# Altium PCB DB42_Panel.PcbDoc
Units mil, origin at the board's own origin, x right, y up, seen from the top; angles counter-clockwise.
Board outline 10094.49 x 7826.77 mil, 8 copper layers (Top Layer, MidLayer1, MidLayer2, GND-Layer5, MidLayer3, 3V3, MidLayer4, Bottom Layer), stack 61.822 mil thick; 0 components, 444 nets, 12 pads, 0 vias.
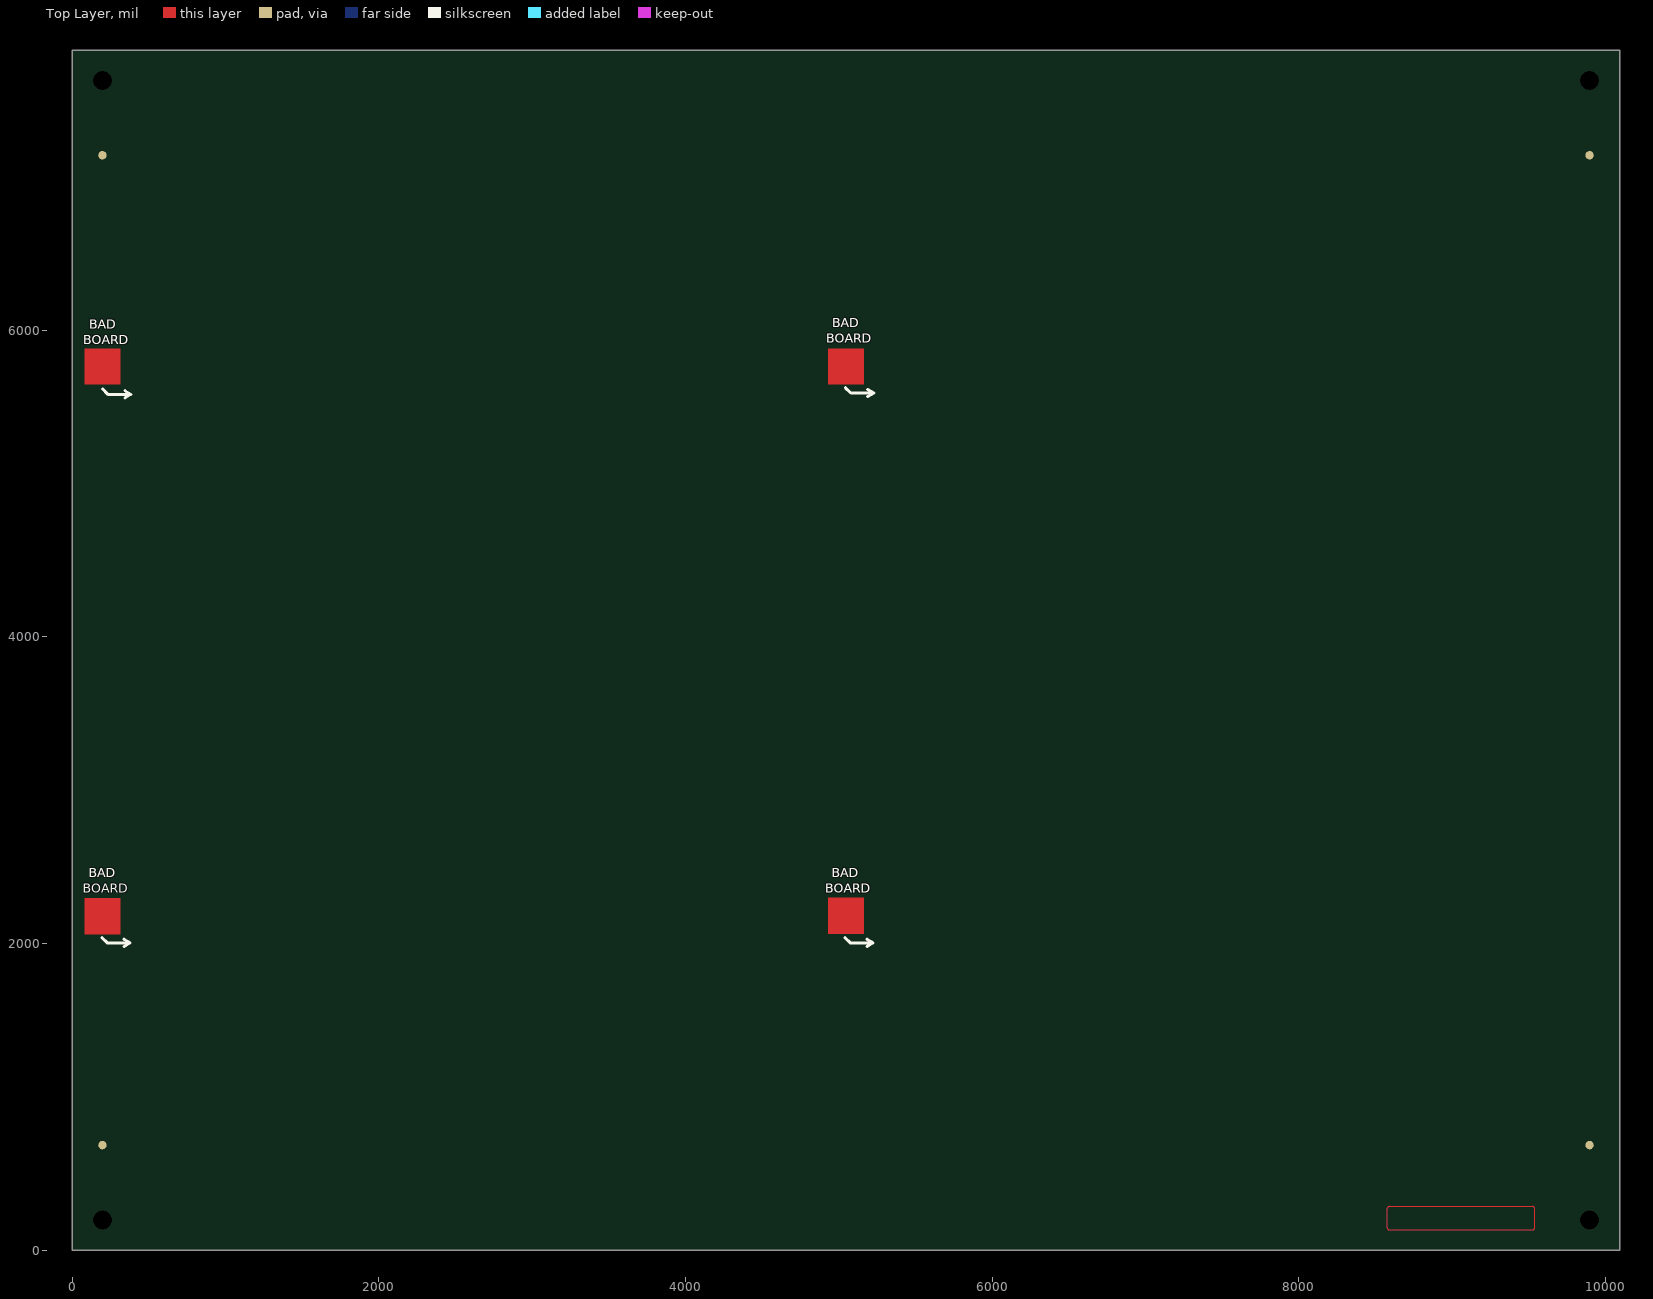
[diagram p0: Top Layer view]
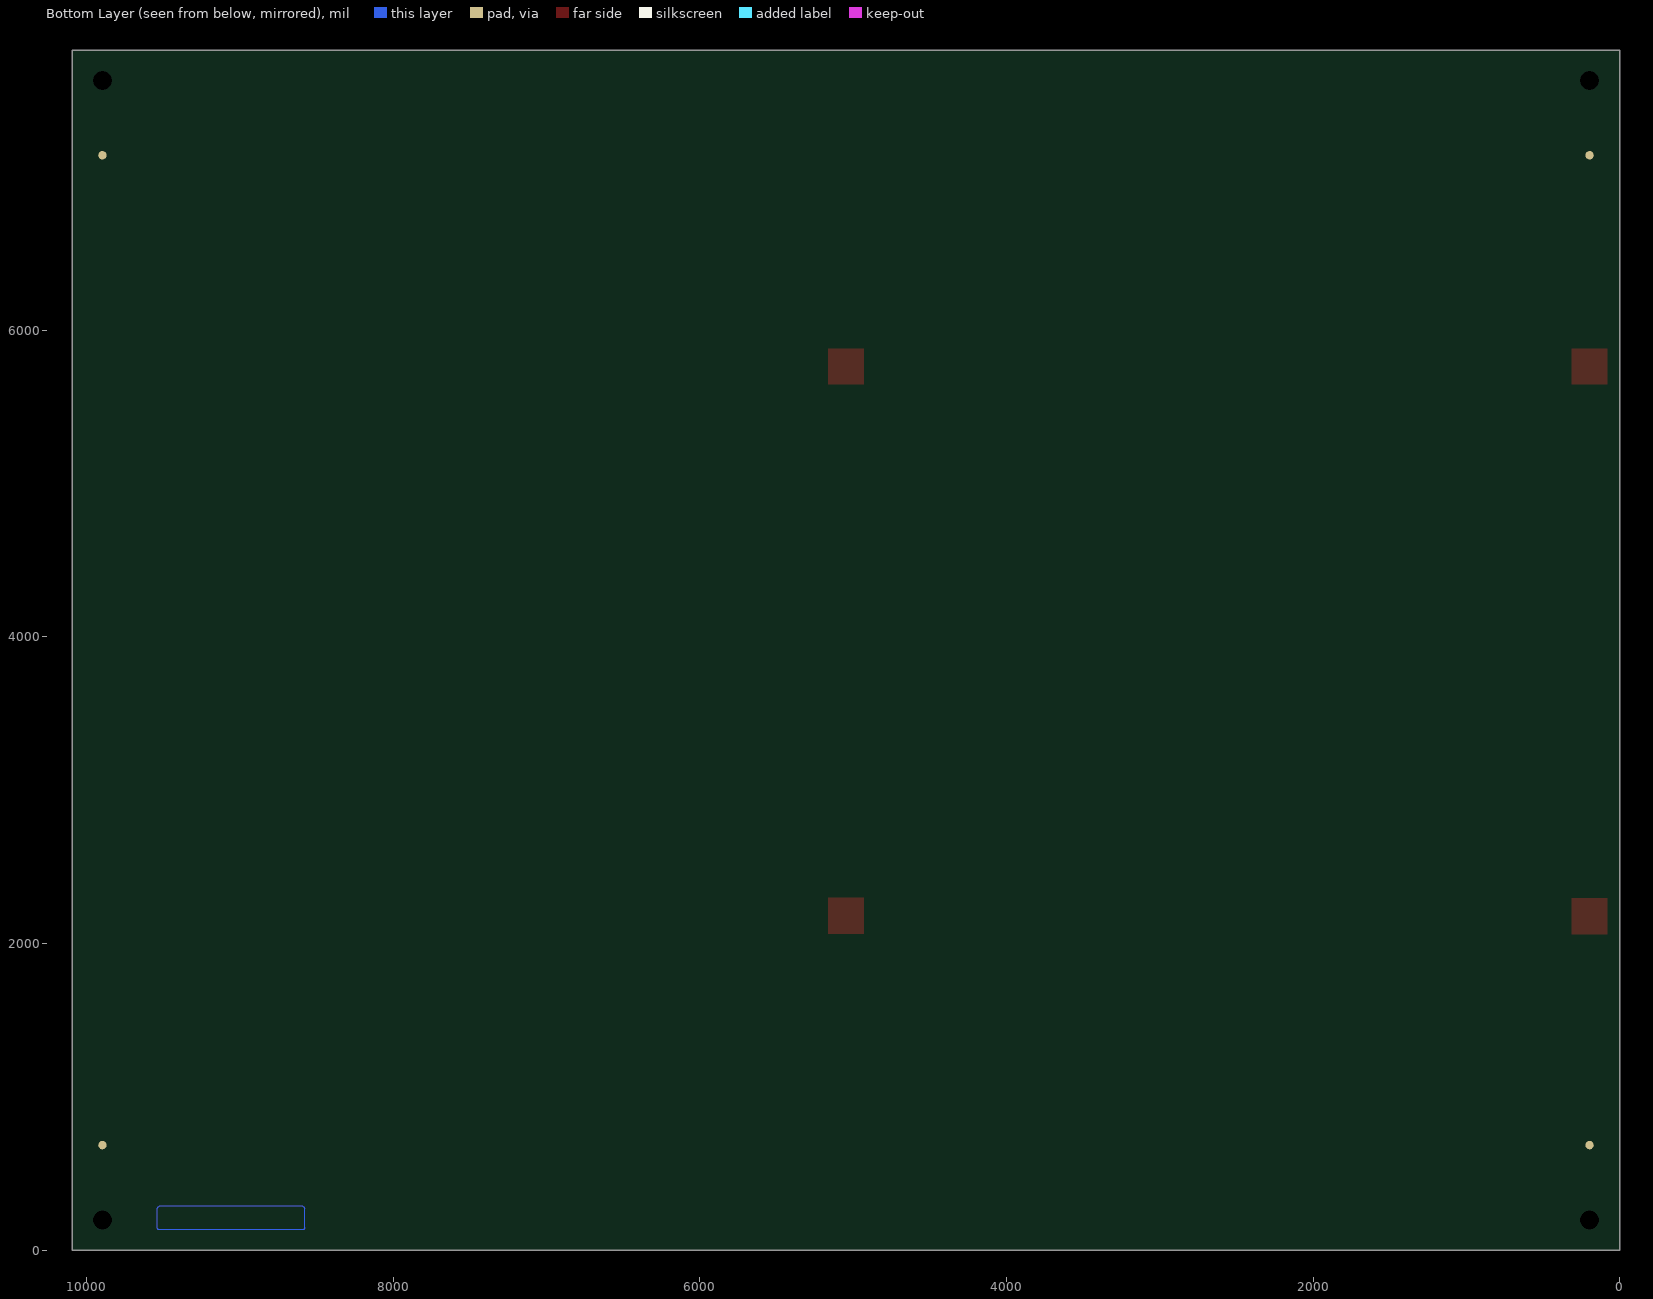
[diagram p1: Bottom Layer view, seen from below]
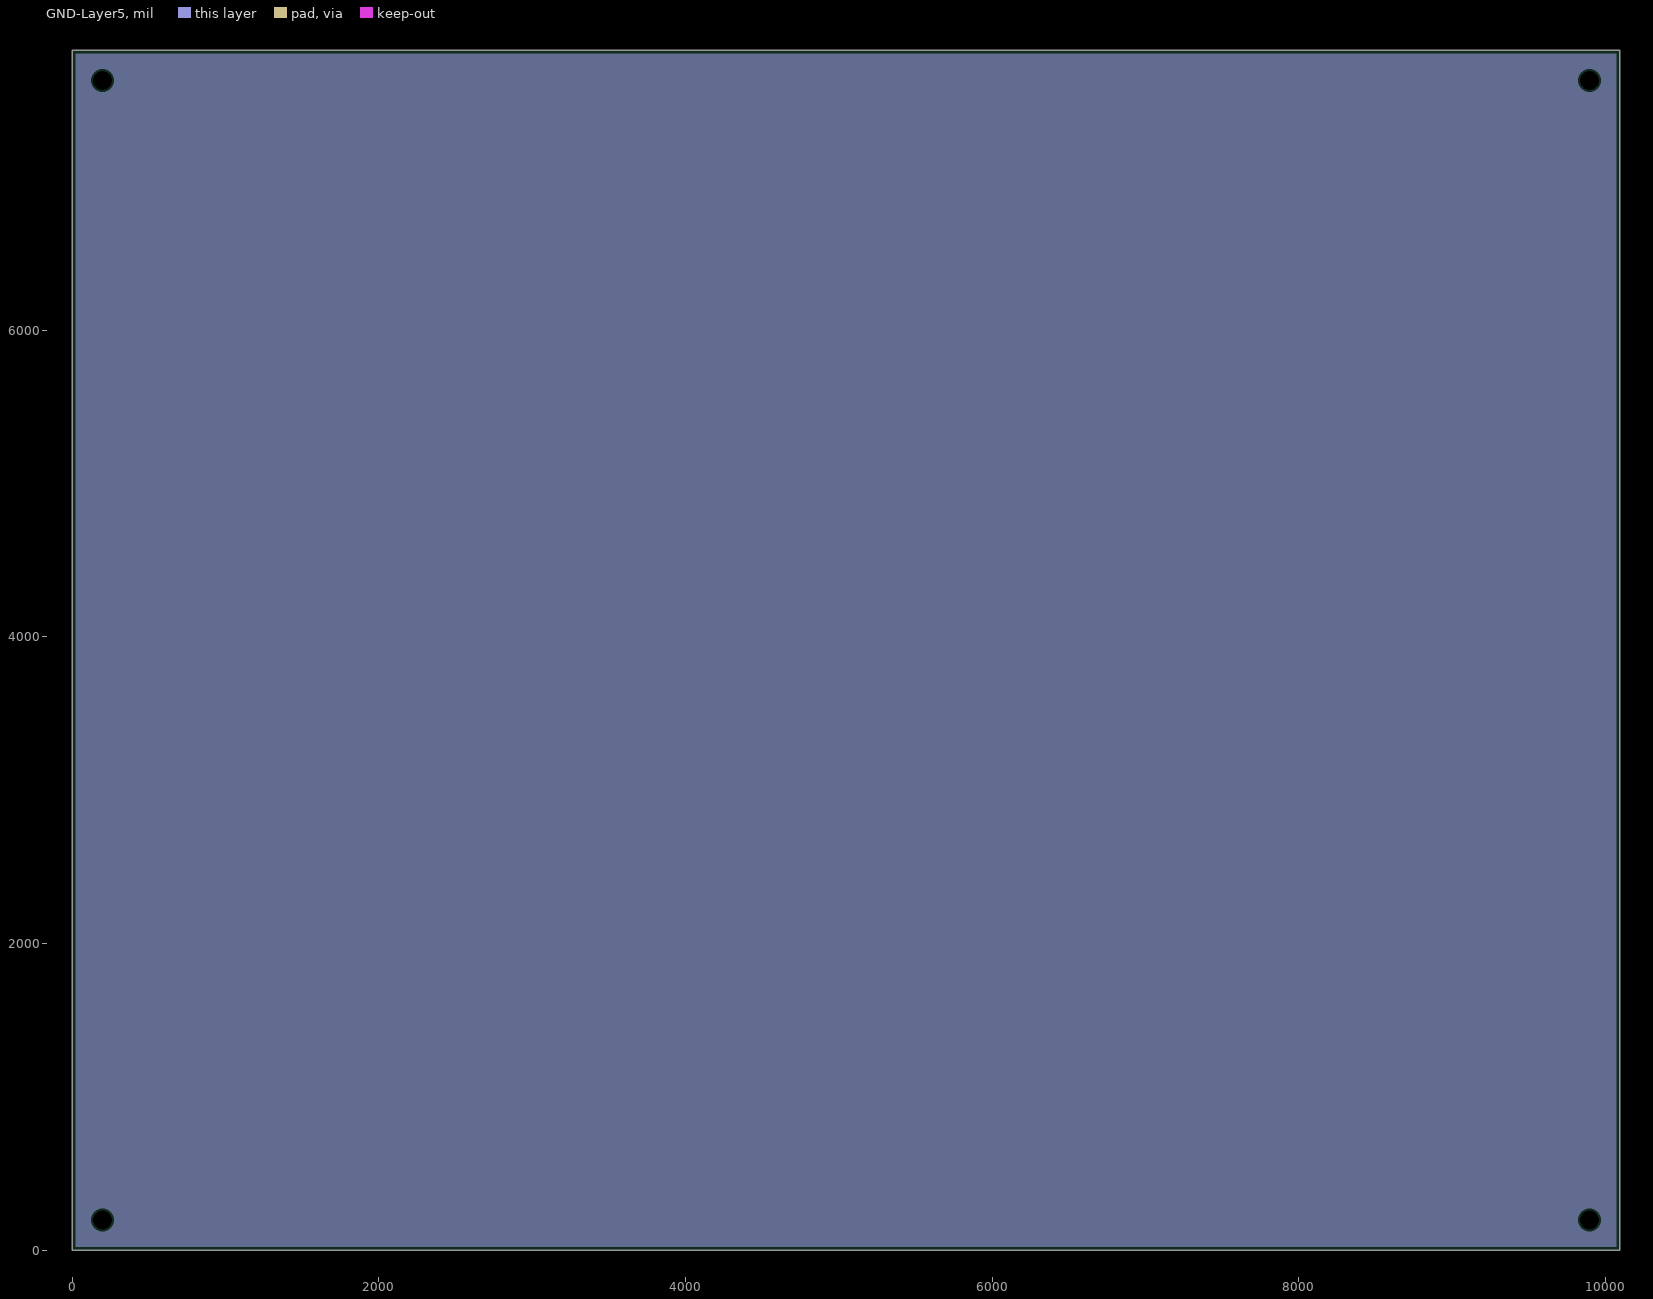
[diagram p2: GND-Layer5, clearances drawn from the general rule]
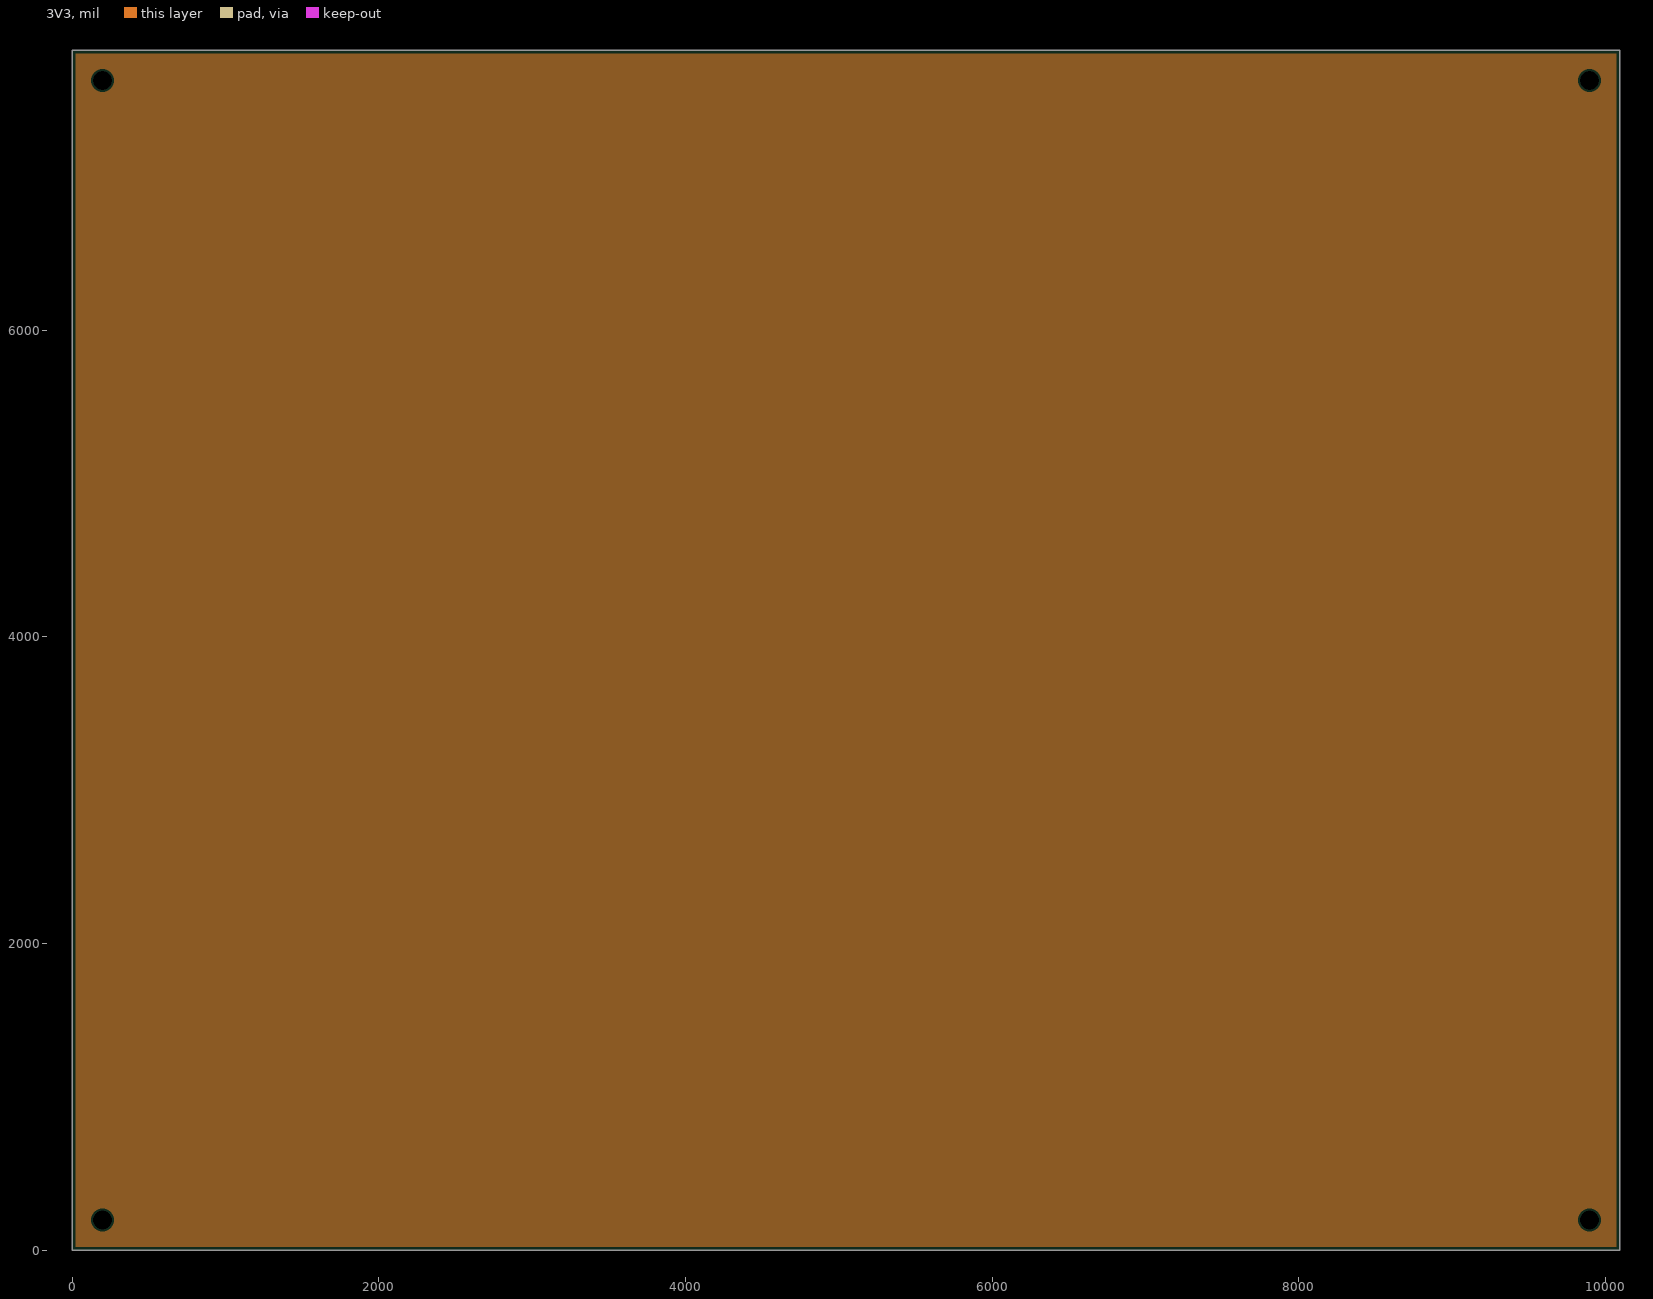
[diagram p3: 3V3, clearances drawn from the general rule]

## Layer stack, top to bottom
Top Layer: signal copper 1.6929
Dielectric: prepreg 5, FR-4, Dk 4.3
MidLayer1: signal copper 1.4016
Dielectric: core 10, FR-4, Dk 4.8
MidLayer2: signal copper 1.4
Dielectric: prepreg 5, FR-4, Dk 4.3
GND-Layer5: plane copper 1.4173
Dielectric: core 10, FR-4, Dk 4.8
MidLayer3: signal copper 1.4
Dielectric: prepreg 5, FR-4, Dk 4.8
3V3: plane copper 1.4173, net 3V3
Dielectric: core 10, FR-4, Dk 4.8
MidLayer4: signal copper 1.4
Dielectric: prepreg 5, FR-4, Dk 4.8
Bottom Layer: signal copper 1.6929

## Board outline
0,0 0,7826.77 10090.55,7826.77 10094.49,7826.77 10094.49,0

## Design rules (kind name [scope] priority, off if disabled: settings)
Clearance Clearance_Poly_Tight [InNamedPolygon('FPGAPWR-TL-1V2') Or InNamedPolygon('FPGAPWR-BL-1V2') Or InNamedPolygon('FPGAPWR-BL-3V3') Or InNamedPolygon('FPGAPWR-BL-2V5A') Or InNamedPolygon('FPGAPWR-BL-2V5B') Or InNamedPolygon('FPGAPWR-BL-2V5C') Or InNamedPolygon('FPGAPWR-BL-2V5D') Or InNamedPolygon('FPGAPWR-ML1-1V2') Or InNamedPolygon('FPGAPWR-BL-2V5E') Or InNamedPolygon('FPGAPWR-BL-3V3' )] p1: gap=5
Clearance Clearance_Polygon [InPolygon] p2: gap=7.87
Clearance "Pad-Pad Clearance Same Net" [IsPad vs IsPad] p3: gap=5
Clearance "Via-Pad Clearance" [IsVia vs IsPad] p4: gap=3.94
Clearance "General Clearance" [All] p5: gap=5
ComponentClearance [All] p1 off: gap=7.87 collisioncheckmode=3 verticalgap=10 showdistances=FALSE
DiffPairsRouting [All] p1: maxlimit=5 minlimit=5 mostfreqgap=5 maxuncoupledlength=200
FabricationTestPointUsage TestPointUsage [All] p1 off: valid=0 allowmultiple=FALSE
FabricationTestpoint Testpoint [All] p1 off: side=3 testpointundercomponent=TRUE minsize=40 maxsize=100 preferedsize=60 minholesize=0 maxholesize=40 preferedholesize=32 testpointgrid=1 allowsidetop=TRUE allowsidebottom=TRUE usegrid=TRUE gridtolerance=0.01
HoleSize [All] p1: absolutevalues=TRUE maxlimit=204.72 minlimit=7.87 maxpercent=80.000 minpercent=20.000
MatchedLengths DiffPair_MatchedLengths [(IsDifferentialPair And (Name = 'DIFF_RX1'))] p1: tolerance=1000 checknetsindiffpair=TRUE checkdiffpairvsdiffpair=TRUE checkothers=TRUE
MinimumAnnularRing MinimumAnnularRing_NonPlated [(ObjectKind = 'Pad') And (HoleDiameter >= '0.7') And (PadIsPlated = 'False')] p1: minimumring=-196.85
MinimumAnnularRing [All] p2: minimumring=5.91
PlaneClearance [All] p1: clearance=11.81
PlaneConnect [All] p1: planeconnectstyle=Direct reliefexpansion=19.68 reliefentries=4 reliefconductorwidth=9.84 reliefairgap=9.84
PolygonConnect PolygonConnect_Via [IsVia] p1: connectstyle=Direct reliefconductorwidth=10 reliefentries=4 polygonreliefangle="90 Angle"
PolygonConnect "PolygonConnect - Heatsink" [(HasFootprint('TO-263') AND InNet('VCCINT'))] p2: connectstyle=Direct reliefconductorwidth=10 reliefentries=4 polygonreliefangle="90 Angle"
PolygonConnect [All] p3: connectstyle=Relief reliefconductorwidth=11.81 reliefentries=4 polygonreliefangle="90 Angle"
RoutingLayers [All] p1: top layer_v5=FALSE mid layer 1_v5=FALSE mid layer 2_v5=FALSE mid layer 3_v5=FALSE mid layer 4_v5=FALSE bottom layer_v5=FALSE
RoutingVias [All] p1: holewidth=11.81 width=23.62 viastyle="Through Hole" minholewidth=11.81 minwidth=23.62 maxholewidth=19.68 maxwidth=35.43
ShortCircuit ShortCircuit_1 [Net = 'No Net' vs Net = 'No Net'] p1: allowed=TRUE
ShortCircuit [All] p2: allowed=FALSE
SilkscreenOverComponentPads [All] p1: minsilkscreentomaskgap=10
SolderMaskExpansion SolderMaskExpansion_Vias [IsVia] p1: expansion=-25.59
SolderMaskExpansion [All] p2: expansion=3.94
Width [All] p1: maxlimit=98.43 minlimit=5 preferedwidth=5
18 further rules are at their usual default settings.

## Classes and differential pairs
component class U_PSU: NT7 R5 R6 TP1 TP2 TP3 TP4
component class U_PSU_MAX1831_1V2: C15 C16 C17 C18 C19 C20 C21 C22 L1_PS R11 R13 R15 R16 R17 TP7 TP8 U2
component class U_Memory_CommonBus: C23_CM C24_CM
net class SRAM_A[20..0]: SRAM_A0 SRAM_A1 SRAM_A2 SRAM_A3 SRAM_A4 SRAM_A5 SRAM_A6 SRAM_A7 SRAM_A8 SRAM_A9 SRAM_A10 SRAM_A11 SRAM_A12 SRAM_A13 SRAM_A14 SRAM_A15 SRAM_A16 SRAM_A17 SRAM_A18
net class EXTEND_C[49..0]: EXTEND_C0 EXTEND_C1 EXTEND_C2 EXTEND_C3 EXTEND_C4 EXTEND_C5 EXTEND_C6 EXTEND_C7 EXTEND_C8 EXTEND_C9 EXTEND_C10 EXTEND_C11 EXTEND_C12 EXTEND_C13 EXTEND_C14 EXTEND_C15 EXTEND_C16 EXTEND_C17 EXTEND_C18 EXTEND_C19 EXTEND_C20 EXTEND_C21 EXTEND_C22 EXTEND_C23 EXTEND_C24 EXTEND_C25 EXTEND_C26 EXTEND_C27 EXTEND_C28 EXTEND_C29 EXTEND_C30 EXTEND_C31 EXTEND_C32 EXTEND_C33 EXTEND_C34 EXTEND_C35 EXTEND_C36 EXTEND_C37 EXTEND_C38 EXTEND_C39 EXTEND_C40 EXTEND_C41 EXTEND_C42 EXTEND_C43 EXTEND_C44 EXTEND_C45 EXTEND_C46 EXTEND_C47 EXTEND_C48 EXTEND_C49
net class EXTEND_B[49..0]: EXTEND_B0 EXTEND_B1 EXTEND_B2 EXTEND_B3 EXTEND_B4 EXTEND_B5 EXTEND_B6 EXTEND_B7 EXTEND_B8 EXTEND_B9 EXTEND_B10 EXTEND_B11 EXTEND_B12 EXTEND_B13 EXTEND_B14 EXTEND_B15 EXTEND_B16 EXTEND_B17 EXTEND_B18 EXTEND_B19 EXTEND_B20 EXTEND_B21 EXTEND_B22 EXTEND_B23 EXTEND_B24 EXTEND_B25 EXTEND_B26 EXTEND_B27 EXTEND_B28 EXTEND_B29 EXTEND_B30 EXTEND_B31 EXTEND_B32 EXTEND_B33 EXTEND_B34 EXTEND_B35 EXTEND_B36 EXTEND_B37 EXTEND_B38 EXTEND_B39 EXTEND_B40 EXTEND_B41 EXTEND_B42 EXTEND_B43 EXTEND_B44 EXTEND_B45 EXTEND_B46 EXTEND_B47 EXTEND_B48 EXTEND_B49
net class EXTEND_A[49..0]: EXTEND_A0 EXTEND_A1 EXTEND_A2 EXTEND_A3 EXTEND_A4 EXTEND_A5 EXTEND_A6 EXTEND_A7 EXTEND_A8 EXTEND_A9 EXTEND_A10 EXTEND_A11 EXTEND_A12 EXTEND_A13 EXTEND_A14 EXTEND_A15 EXTEND_A16 EXTEND_A17 EXTEND_A18 EXTEND_A19 EXTEND_A20 EXTEND_A21 EXTEND_A22 EXTEND_A23 EXTEND_A24 EXTEND_A25 EXTEND_A26 EXTEND_A27 EXTEND_A28 EXTEND_A29 EXTEND_A30 EXTEND_A31 EXTEND_A32 EXTEND_A33 EXTEND_A34 EXTEND_A35 EXTEND_A36 EXTEND_A37 EXTEND_A38 EXTEND_A39 EXTEND_A40 EXTEND_A41 EXTEND_A42 EXTEND_A43 EXTEND_A44 EXTEND_A45 EXTEND_A46 EXTEND_A47 EXTEND_A48 EXTEND_A49
net class DAU_TFT_RED[4..0]: DAU_TFT_RED0 DAU_TFT_RED1 DAU_TFT_RED2 DAU_TFT_RED3 DAU_TFT_RED4
net class DAU_TFT_GREEN[5..0]: DAU_TFT_GREEN0 DAU_TFT_GREEN1 DAU_TFT_GREEN2 DAU_TFT_GREEN3 DAU_TFT_GREEN4 DAU_TFT_GREEN5
net class DAU_TFT_CL[3..1]: DAU_TFT_CL1 DAU_TFT_CL2 DAU_TFT_CL3
net class DAU_TFT_BLUE[4..0]: DAU_TFT_BLUE0 DAU_TFT_BLUE1 DAU_TFT_BLUE2 DAU_TFT_BLUE3 DAU_TFT_BLUE4
net class BUS_A[24..1]: BUS_A1 BUS_A2 BUS_A3 BUS_A4 BUS_A5 BUS_A6 BUS_A7 BUS_A8 BUS_A9 BUS_A10 BUS_A11 BUS_A12 BUS_A13 BUS_A14 BUS_A15 BUS_A16 BUS_A17 BUS_A18 BUS_A19 BUS_A20 BUS_A21 BUS_A22 BUS_A23 BUS_A24
component class U_SRAM_Common: C15_CM C16_CM C17_CM C18_CM C19_CM C20_CM C21_CM C22_CM U4_CM U5_CM
component class U_SDRAM: C7_CM C8_CM C9_CM C10_CM C11_CM C12_CM C13_CM C14_CM U2_CM U3_CM
component class U_FLASH: C1_CM C2_CM C3_CM C4_CM C5_CM C6_CM U1_CM
component class U_Bypass_Board: C1_MB C1_PSU C2_MB C3_MB C4_MB C6_MB
component class U_Bypass_3V3: C38_FP C39_FP C40_FP C41_FP C42_FP C43_FP C44_FP C45_FP C46_FP C47_FP C48_FP C49_FP C50_FP C51_FP C52_FP C53_FP C54_FP C55_FP C56_FP C57_FP C58_FP C59_FP C60_FP C61_FP C62_FP C63_FP C64_FP C65_FP C66_FP C67_FP C68_FP C69_FP C70_FP C71_FP C72_FP C73_FP C74_FP C75_FP C76_FP C77_FP C78_FP C79_FP C80_FP C81_FP C82_FP C83_FP C84_FP C85_FP C86_FP C87_FP C88_FP C89_FP C90_FP C91_FP C92_FP C93_FP C94_FP C95_FP C96_FP C97_FP C98_FP C99_FP C100_FP C101_FP C102_FP C103_FP C104_FP C105_FP C106_FP
component class U_SRAM_Free: C1_M C2_M C2B C3_M C4_M C4B C5_M C5B C6_M C7_M C7B C8_M C8B C9_M C9B C10_M C10B C12_M C12B U7B U8B U18 U20
component class U_MotherBoardConnectors: HDR_B HDR_L HDR_T NT1
component class U_LEDS: C98 LED1 LED2 R19 R21 U9
component class U_SPARTAN3: NT2 NT3 NT4 NT5 NT6 NT8 R1 R2 R3 R4 R7 R8 R12 R14 R18 R20 R22 R23 R24 R25 R26 R27 U1
net class BUS_D[31..0]: BUS_D0 BUS_D1 BUS_D2 BUS_D3 BUS_D4 BUS_D5 BUS_D6 BUS_D7 BUS_D8 BUS_D9 BUS_D10 BUS_D11 BUS_D12 BUS_D13 BUS_D14 BUS_D15 BUS_D16 BUS_D17 BUS_D18 BUS_D19 BUS_D20 BUS_D21 BUS_D22 BUS_D23 BUS_D24 BUS_D25 BUS_D26 BUS_D27 BUS_D28 BUS_D29 BUS_D30 BUS_D31
net class BUS_NBE[3..0]: BUS_NBE0 BUS_NBE1 BUS_NBE2 BUS_NBE3
net class DIP[7..0]: DIP0 DIP1 DIP2 DIP3 DIP4 DIP5 DIP6 DIP7
net class FPGA_ID[3..0]: FPGA_ID0 FPGA_ID1 FPGA_ID2 FPGA_ID3
net class FPGA_M[2..0]: FPGA_M0 FPGA_M1 FPGA_M2
net class IO[35..0]: IO0 IO1 IO2 IO3 IO4 IO5 IO6 IO7 IO8 IO9 IO10 IO11 IO12 IO13 IO14 IO15 IO16 IO17 IO18 IO19 IO20 IO21 IO22 IO23 IO24 IO25 IO26 IO27 IO28 IO29 IO30 IO31 IO32 IO33 IO34 IO35
net class LED[7..0]: LED0 LED1 LED2 LED3 LED4 LED5 LED6 LED7
net class SRAM_D[31..0]: SRAM_D0 SRAM_D1 SRAM_D2 SRAM_D3 SRAM_D4 SRAM_D5 SRAM_D6 SRAM_D7 SRAM_D8 SRAM_D9 SRAM_D10 SRAM_D11 SRAM_D12 SRAM_D13 SRAM_D14 SRAM_D15 SRAM_D16 SRAM_D17 SRAM_D18 SRAM_D19 SRAM_D20 SRAM_D21 SRAM_D22 SRAM_D23 SRAM_D24 SRAM_D25 SRAM_D26 SRAM_D27 SRAM_D28 SRAM_D29 SRAM_D30 SRAM_D31
net class SRAM_NBE[3..0]: SRAM_NBE0 SRAM_NBE1 SRAM_NBE2 SRAM_NBE3
net class SW[4..0]: SW0 SW1 SW2 SW3 SW4
differential pair class DIFF_IN: DIFF_RX0 DIFF_RX1 DIFF_RX2 DIFF_RX3
differential pair class DIFF_OUT: DIFF_TX0 DIFF_TX1 DIFF_TX2 DIFF_TX3
net class PWRNET: 1V2 3V3 5V0 AGND GND
component class U_FPGA_Power: C1_PL C2_PL C3_PL C4_PL C5_PL C6_PL C7_PL C8_PL C9_PL C10_PL C11_PL C12_PL C13_PL C14_PL C15_PL C16_PL L2 L3 L4 L5
component class COMP_1V2: C15 C17 C18 C19 C20 C21 C22 L1_PS NT1 NT7 R13 R17
component class COMP_PLL: C1_PL C2_PL C3_PL C4_PL C5_PL C6_PL C7_PL C8_PL C9_PL C10_PL C11_PL C12_PL C13_PL C14_PL C15_PL C16_PL L2 L3 L4 L5
component class U_Bypass_1V2: C1_FP C2_FP C3_FP C4_FP C5_FP C6_FP C7_FP C8_FP C9_FP C10_FP C11_FP C12_FP C13_FP C14_FP C15_FP C16_FP C17_FP C18_FP C19_FP C20_FP C21_FP C22_FP C23_FP C24_FP C25_FP C26_FP C27_FP C28_FP C29_FP C30_FP C31_FP
net class FPGACONF: CONF_DONE DATA0 DCLK FPGA_CCLK FPGA_DIN FPGA_DONE FPGA_INIT FPGA_M0 FPGA_M1 FPGA_PROGRAM FPGA_TCK FPGA_TDI FPGA_TDO FPGA_TMS MSEL0 MSEL1 NCONFIG NSTATUS TCK TDI TDO TMS
net class PLL: VCCA_PLL1 VCCA_PLL2 VCCA_PLL3 VCCA_PLL4
component class DaughterBoard_FPGA: MH1 MH2 MH3
component class MOUNTS-PCB: MH1 MH2 MH3

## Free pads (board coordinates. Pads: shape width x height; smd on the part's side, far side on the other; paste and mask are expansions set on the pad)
  round 106 hole 126 unplated mask+35: 126N(196.85,196.85) 126N(196.85,7629.92) 126N(9897.64,7629.92)
  round 105.98 hole 125.98 unplated mask+35: 126N(9897.64,196.85)
  round 55 smd far side paste-100 mask+52: fidbot(196.85,685.04) fidbot(196.85,7141.73) fidbot(9897.64,685.04) fidbot(9897.64,7141.73)
  round 55 smd paste-100 mask+52: fidtop(196.85,685.04) fidtop(196.85,7141.73) fidtop(9897.64,685.04) fidtop(9897.64,7141.73)

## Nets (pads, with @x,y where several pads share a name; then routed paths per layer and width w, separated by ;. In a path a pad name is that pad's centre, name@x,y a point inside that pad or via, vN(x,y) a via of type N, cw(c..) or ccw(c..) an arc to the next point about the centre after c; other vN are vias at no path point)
1V2: 
3V3: 
5V0: 
AGND: 
BUS_A1: 
BUS_A2: 
BUS_A3: 
BUS_A4: 
BUS_A5: 
BUS_A6: 
BUS_A7: 
BUS_A8: 
BUS_A9: 
BUS_A10: 
BUS_A11: 
BUS_A12: 
BUS_A13: 
BUS_A14: 
BUS_A15: 
BUS_A16: 
BUS_A17: 
BUS_A18: 
BUS_A19: 
BUS_A20: 
BUS_A21: 
BUS_A22: 
BUS_A23: 
BUS_A24: 
BUS_D0: 
BUS_D1: 
BUS_D2: 
BUS_D3: 
BUS_D4: 
BUS_D5: 
BUS_D6: 
BUS_D7: 
BUS_D8: 
BUS_D9: 
BUS_D10: 
BUS_D11: 
BUS_D12: 
BUS_D13: 
BUS_D14: 
BUS_D15: 
BUS_D16: 
BUS_D17: 
BUS_D18: 
BUS_D19: 
BUS_D20: 
BUS_D21: 
BUS_D22: 
BUS_D23: 
BUS_D24: 
BUS_D25: 
BUS_D26: 
BUS_D27: 
BUS_D28: 
BUS_D29: 
BUS_D30: 
BUS_D31: 
BUS_FLASH_NBUSY: 
BUS_FLASH_NCS: 
BUS_FLASH_NRESET: 
BUS_NBE0: 
BUS_NBE1: 
BUS_NBE2: 
BUS_NBE3: 
BUS_NOE: 
BUS_NWE: 
BUS_RAM_NCS: 
BUS_SDRAM_CKE: 
BUS_SDRAM_CLK: 
BUS_SDRAM_NCAS: 
BUS_SDRAM_NCS: 
BUS_SDRAM_NRAS: 
BUZZER: 
CAN_RXD: 
CAN_TXD: 
COMP: 
CONF_DONE: 
DATA0: 
DAU_RESET_SW: 
DAU_SPARE: 
DAU_TFT_BLIGHT: 
DAU_TFT_BLUE0: 
DAU_TFT_BLUE1: 
DAU_TFT_BLUE2: 
DAU_TFT_BLUE3: 
DAU_TFT_BLUE4: 
DAU_TFT_CL1: 
DAU_TFT_CL2: 
DAU_TFT_CL3: 
DAU_TFT_DISP_ON: 
DAU_TFT_GREEN0: 
DAU_TFT_GREEN1: 
DAU_TFT_GREEN2: 
DAU_TFT_GREEN3: 
DAU_TFT_GREEN4: 
DAU_TFT_GREEN5: 
DAU_TFT_IRQ: 
DAU_TFT_M: 
DAU_TFT_MUX: 
DAU_TFT_POL: 
DAU_TFT_RED0: 
DAU_TFT_RED1: 
DAU_TFT_RED2: 
DAU_TFT_RED3: 
DAU_TFT_RED4: 
DAU_TFT_STH: 
DAU_TFT_STV: 
DCLK: 
DIP0: 
DIP1: 
DIP2: 
DIP3: 
DIP4: 
DIP5: 
DIP6: 
DIP7: 
EXTEND_A0: 
EXTEND_A1: 
EXTEND_A2: 
EXTEND_A3: 
EXTEND_A4: 
EXTEND_A5: 
EXTEND_A6: 
EXTEND_A7: 
EXTEND_A8: 
EXTEND_A9: 
EXTEND_A10: 
EXTEND_A11: 
EXTEND_A12: 
EXTEND_A13: 
EXTEND_A14: 
EXTEND_A15: 
EXTEND_A16: 
EXTEND_A17: 
EXTEND_A18: 
EXTEND_A19: 
EXTEND_A20: 
EXTEND_A21: 
EXTEND_A22: 
EXTEND_A23: 
EXTEND_A24: 
EXTEND_A25: 
EXTEND_A26: 
EXTEND_A27: 
EXTEND_A28: 
EXTEND_A29: 
EXTEND_A30: 
EXTEND_A31: 
EXTEND_A32: 
EXTEND_A33: 
EXTEND_A34: 
EXTEND_A35: 
EXTEND_A36: 
EXTEND_A37: 
EXTEND_A38: 
EXTEND_A39: 
EXTEND_A40: 
EXTEND_A41: 
EXTEND_A42: 
EXTEND_A43: 
EXTEND_A44: 
EXTEND_A45: 
EXTEND_A46: 
EXTEND_A47: 
EXTEND_A48: 
EXTEND_A49: 
EXTEND_B0: 
EXTEND_B1: 
EXTEND_B2: 
EXTEND_B3: 
EXTEND_B4: 
EXTEND_B5: 
EXTEND_B6: 
EXTEND_B7: 
EXTEND_B8: 
EXTEND_B9: 
EXTEND_B10: 
EXTEND_B11: 
EXTEND_B12: 
EXTEND_B13: 
EXTEND_B14: 
EXTEND_B15: 
EXTEND_B16: 
EXTEND_B17: 
EXTEND_B18: 
EXTEND_B19: 
EXTEND_B20: 
EXTEND_B21: 
EXTEND_B22: 
EXTEND_B23: 
EXTEND_B24: 
EXTEND_B25: 
EXTEND_B26: 
EXTEND_B27: 
EXTEND_B28: 
EXTEND_B29: 
EXTEND_B30: 
EXTEND_B31: 
EXTEND_B32: 
EXTEND_B33: 
EXTEND_B34: 
EXTEND_B35: 
EXTEND_B36: 
EXTEND_B37: 
EXTEND_B38: 
EXTEND_B39: 
EXTEND_B40: 
EXTEND_B41: 
EXTEND_B42: 
EXTEND_B43: 
EXTEND_B44: 
EXTEND_B45: 
EXTEND_B46: 
EXTEND_B47: 
EXTEND_B48: 
EXTEND_B49: 
EXTEND_C0: 
EXTEND_C1: 
EXTEND_C2: 
EXTEND_C3: 
EXTEND_C4: 
EXTEND_C5: 
EXTEND_C6: 
EXTEND_C7: 
EXTEND_C8: 
EXTEND_C9: 
EXTEND_C10: 
EXTEND_C11: 
EXTEND_C12: 
EXTEND_C13: 
EXTEND_C14: 
EXTEND_C15: 
EXTEND_C16: 
EXTEND_C17: 
EXTEND_C18: 
EXTEND_C19: 
EXTEND_C20: 
EXTEND_C21: 
EXTEND_C22: 
EXTEND_C23: 
EXTEND_C24: 
EXTEND_C25: 
EXTEND_C26: 
EXTEND_C27: 
EXTEND_C28: 
EXTEND_C29: 
EXTEND_C30: 
EXTEND_C31: 
EXTEND_C32: 
EXTEND_C33: 
EXTEND_C34: 
EXTEND_C35: 
EXTEND_C36: 
EXTEND_C37: 
EXTEND_C38: 
EXTEND_C39: 
EXTEND_C40: 
EXTEND_C41: 
EXTEND_C42: 
EXTEND_C43: 
EXTEND_C44: 
EXTEND_C45: 
EXTEND_C46: 
EXTEND_C47: 
EXTEND_C48: 
EXTEND_C49: 
FB: 
FPGA_CCLK: 
FPGA_CLK: 
FPGA_CLK1: 
FPGA_CLK2: 
FPGA_DIN: 
FPGA_DONE: 
FPGA_ID0: 
FPGA_ID1: 
FPGA_ID2: 
FPGA_ID3: 
FPGA_INIT: 
FPGA_INSTALLED: 
FPGA_M0: 
FPGA_M1: 
FPGA_M2: 
FPGA_PROG_CLK: 
FPGA_PROG_PWR_ON: 
FPGA_PROGRAM: 
FPGA_TCK: 
FPGA_TDI: 
FPGA_TDO: 
FPGA_TMS: 
GND: 
IO0: 
IO1: 
IO2: 
IO3: 
IO4: 
IO5: 
IO6: 
IO7: 
IO8: 
IO9: 
IO10: 
IO11: 
IO12: 
IO13: 
IO14: 
IO15: 
IO16: 
IO17: 
IO18: 
IO19: 
IO20: 
IO21: 
IO22: 
IO23: 
IO24: 
IO25: 
IO26: 
IO27: 
IO28: 
IO29: 
IO30: 
IO31: 
IO32: 
IO33: 
IO34: 
IO35: 
KBCLOCK: 
KBDATA: 
LED0: 
LED1: 
LED2: 
LED3: 
LED4: 
LED5: 
LED6: 
LED7: 
LED_PGM: 
LED_PWR: 
LX: 
MOUSECLOCK: 
MOUSEDATA: 
MSEL0: 
MSEL1: 
NCONFIG: 
NetLED2_1: 
NetR15_1: 
NEXUS_TCK: 
NEXUS_TDI: 
NEXUS_TDO: 
NEXUS_TMS: 
NSTATUS: 
REF_1V2: 
REF_CLK: 
RS232_CTS: 
RS232_RTS: 
RS232_RX: 
RS232_TX: 
SCL: 
SDA: 
SDRAM_FEEDBACK: 
SPI_CLK: 
SPI_DIN: 
SPI_DOUT: 
SPI_MODE: 
SPI_SEL: 
SRAM_A0: 
SRAM_A1: 
SRAM_A2: 
SRAM_A3: 
SRAM_A4: 
SRAM_A5: 
SRAM_A6: 
SRAM_A7: 
SRAM_A8: 
SRAM_A9: 
SRAM_A10: 
SRAM_A11: 
SRAM_A12: 
SRAM_A13: 
SRAM_A14: 
SRAM_A15: 
SRAM_A16: 
SRAM_A17: 
SRAM_A18: 
SRAM_D0: 
SRAM_D1: 
SRAM_D2: 
SRAM_D3: 
SRAM_D4: 
SRAM_D5: 
SRAM_D6: 
SRAM_D7: 
SRAM_D8: 
SRAM_D9: 
SRAM_D10: 
SRAM_D11: 
SRAM_D12: 
SRAM_D13: 
SRAM_D14: 
SRAM_D15: 
SRAM_D16: 
SRAM_D17: 
SRAM_D18: 
SRAM_D19: 
SRAM_D20: 
SRAM_D21: 
SRAM_D22: 
SRAM_D23: 
SRAM_D24: 
SRAM_D25: 
SRAM_D26: 
SRAM_D27: 
SRAM_D28: 
SRAM_D29: 
SRAM_D30: 
SRAM_D31: 
SRAM_NBE0: 
SRAM_NBE1: 
SRAM_NBE2: 
SRAM_NBE3: 
SRAM_NCS: 
SRAM_NOE: 
SRAM_NWE: 
STATUS_LED: 
SW0: 
SW1: 
SW2: 
SW3: 
SW4: 
TCK: 
TDI: 
TDO: 
TMS: 
TOFF: 
VCCA_PLL1: 
VCCA_PLL2: 
VCCA_PLL3: 
VCCA_PLL4: 
VCCX: 
VCCX_REF: 
VFILT: 

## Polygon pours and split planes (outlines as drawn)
no net on GND-Layer5 (split plane): 10074.39,20.1 20.1,20.1 20.1,7806.67 10074.39,7806.67
3V3 on 3V3 (split plane): 10074.39,20.1 20.1,20.1 20.1,7806.67 10074.39,7806.67

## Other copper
Top Layer:
  rectangle: 78.74,5645.67 314.96,5881.89
  rectangle: 4929.13,5645.67 5165.35,5881.89
  rectangle: 4929.13,2062.99 5165.35,2299.21
  rectangle: 78.74,2059.06 314.96,2295.28
  rectangle: 78.74,5645.67 314.96,5881.89
  rectangle: 4929.13,5645.67 5165.35,5881.89
  rectangle: 4929.13,2062.99 5165.35,2299.21
  rectangle: 78.74,2059.06 314.96,2295.28
Multi-Layer:
  lines w8: 8579.44,144.44 ccw(c8592.44,144.44) 8592.44,131.44 9525.77,131.44 ccw(c9525.77,144.44) 9538.77,144.44 9538.77,271.95 ccw(c9525.77,271.95) 9525.77,284.95 8592.44,284.95 ccw(c8592.44,271.95) 8579.44,271.95 8579.44,144.44
  text "DB42SVN9250" at 8606.44,160.22 h150

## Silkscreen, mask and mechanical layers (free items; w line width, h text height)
Top Overlay:
  lines w20: 228.35,2003.94 377.95,2003.94 ; 228.35,2003.94 192.91,2039.37 228.35,2003.94 ; 228.35,2003.94 377.95,2003.94 ; 232.28,5582.68 196.85,5618.11 232.28,5582.68 ; 232.28,5582.68 381.89,5582.68 ; 232.28,5582.68 381.89,5582.68 ; 377.95,2003.94 338.58,2027.56 377.95,2003.94 ; 377.95,2003.94 338.58,1980.31 377.95,2003.94 ; 381.89,5582.68 342.52,5559.06 381.89,5582.68 ; 381.89,5582.68 342.52,5606.3 381.89,5582.68 ; 5074.8,2003.94 5224.41,2003.94 ; 5074.8,2003.94 5039.37,2039.37 5074.8,2003.94 ; 5074.8,2003.94 5224.41,2003.94 ; 5078.74,5590.55 5228.35,5590.55 ; 5078.74,5590.55 5043.31,5625.98 5078.74,5590.55 ; 5078.74,5590.55 5228.35,5590.55 ; 5224.41,2003.94 5185.04,2027.56 5224.41,2003.94 ; 5224.41,2003.94 5185.04,1980.31 5224.41,2003.94 ; 5228.35,5590.55 5188.98,5614.17 5228.35,5590.55 ; 5228.35,5590.55 5188.98,5566.93 5228.35,5590.55
  text "BAD" at 4956.69,6019.68 h60
  text "BAD" at 4956.69,6019.68 h60
  text "BAD" at 110.24,6011.81 h60
  text "BAD" at 110.24,6011.81 h60
  text "BOARD" at 4917.32,5917.32 h60
  text "BOARD" at 4917.32,5917.32 h60
  text "BOARD" at 70.87,5909.45 h60
  text "BOARD" at 70.87,5909.45 h60
  text "BAD" at 106.3,2433.07 h60
  text "BAD" at 106.3,2433.07 h60
  text "BAD" at 4952.76,2433.07 h60
  text "BAD" at 4952.76,2433.07 h60
  text "BOARD" at 66.93,2330.71 h60
  text "BOARD" at 4913.39,2330.71 h60
  text "BOARD" at 4913.39,2330.71 h60
Top Solder:
  rectangle: 78.74,5645.67 314.96,5881.89
  rectangle: 4929.13,5645.67 5165.35,5881.89
  rectangle: 4929.13,2062.99 5165.35,2299.21
  rectangle: 78.74,2059.06 314.96,2295.28
  rectangle: 78.74,5645.67 314.96,5881.89
  rectangle: 4929.13,5645.67 5165.35,5881.89
  rectangle: 4929.13,2062.99 5165.35,2299.21
  rectangle: 78.74,2059.06 314.96,2295.28
  lines w8: 8579.44,144.44 ccw(c8592.44,144.44) 8592.44,131.44 9525.77,131.44 ccw(c9525.77,144.44) 9538.77,144.44 9538.77,271.95 ccw(c9525.77,271.95) 9525.77,284.95 8592.44,284.95 ccw(c8592.44,271.95) 8579.44,271.95 8579.44,144.44
  text "DB42SVN9250" at 8606.44,160.22 h150
Bottom Solder:
  lines w8: 8579.44,144.44 ccw(c8592.44,144.44) 8592.44,131.44 9525.77,131.44 ccw(c9525.77,144.44) 9538.77,144.44 9538.77,271.95 ccw(c9525.77,271.95) 9525.77,284.95 8592.44,284.95 ccw(c8592.44,271.95) 8579.44,271.95 8579.44,144.44
  text "DB42SVN9250" at 8606.44,160.22 h150
6. FabNotes:
  drawing of 1029 lines, arcs and shapes, not listed
  text "DAUGHTER-BOARD PANEL" at 12915,11218.98 h49.21
  text "DESIGN INFORMATION" at 10700.86,11218.22 h49.21
  text "BOARD NAME:" at 12180.86,11218.22 h49.21
  text "BOARD TECHNOLOGY" at 10700.86,11118.22 h49.21
  text "BOARD SIZE (REFER ALSO PROFILING INFORMATION)" at 12600.86,11118.22 h49.21
  text "5.0" at 10784.37,11032.05 h49.21
  text "256.40" at 12707.95,11028.7 h49.21
  text "12.0" at 11322.87,11025.24 h49.21
  text "198.80mm" at 13613.46,11024.76 h49.21
  text "5.0" at 11872.87,11020.24 h49.21
  text "RECOMMENDED LAYUP" at 7167.32,10999.72 h49.21
  text "X" at 13335.86,10998.22 h49.21
  text "(MIN. TRACK/   PADS  /   CLEARANCE     IN 0.001'')" at 10640.86,10918.22 h49.21
  text "MINIMUM ANNULAR RING 0.05MM (0.002'') EXTERNAL PER IPC-2221 CLASS 3 LEVEL C AND IS THE" at 10700.87,10818.23 h49.21
  text "MANUFACTURING REGISTRATION ALLOWANCE" at 10700.86,10728.22 h49.21
  text "LAND SIZE CALCULATION MINIMUM - NOMINAL HOLE SIZE + 0.508MM (0.020'')" at 10700.86,10618.22 h49.21
  text "LAYER STACK CONFIGURATION" at 6747.09,10595.28 h49.21
  text "CIRCUIT TYPE:" at 10700.86,10438.22 h49.21
  text "SS" at 11600.86,10438.22 h49.21
  text "DS" at 12300.86,10438.22 h49.21
  text "X" at 12875.86,10438.22 h49.21
  text "PTH" at 13000.86,10438.22 h49.21
  text "ML" at 13430.86,10438.22 h49.21
  text "X" at 13580.86,10438.22 h49.21
  text "No. of Layers" at 13700.86,10438.22 h49.21
  text "8" at 14384.37,10432.05 h49.21
  text "FINGER CONNECTOR DIM PER:" at 10700.86,10318.22 h49.21
  text "AS SHOWN" at 13700.86,10318.22 h49.21
  text "8 LAYER BUILD" at 7178.8,10313.28 h49.21
  text "No. OFF TOTAL" at 11360.86,10208.22 h49.21
  text "ONE SIDE" at 13000.86,10208.22 h49.21
  text "BOTH SIDES" at 13700.86,10198.22 h49.21
  text "X" at 12177.72,10097.15 h49.21
  text "VIAS:" at 10700.86,10093.22 h49.21
  text "NONE" at 11150.86,10093.22 h49.21
  text "X" at 11480.86,10093.22 h49.21
  text "FEED THRU'" at 11600.86,10093.22 h49.21
  text "TENTED" at 12300.86,10093.22 h49.21
  text "BURIED LAYER SEQUENCE" at 13000.86,10093.22 h49.21
  text "-  COPPER CLAD" at 7849.09,9984 h29.53
  text "-  35 Micron H.T.E 1.4mil" at 8277.09,9984.02 h29.53
  text "TL" at 6803.56,9979 h49.21
  text "UNIQUE DRILL" at 11600.86,9973.22 h49.21
  text "2 SIZE" at 12300.86,9973.22 h49.21
  text "BLIND LAYER SEQUENCE" at 13000.86,9973.22 h49.21
  text "TOP LAYER" at 6302.33,9956 h49.21
  text "-  PRE-PREG" at 7874.09,9929 h29.53
  text "-  1080 5mil" at 8277.09,9927.99 h29.53
  text "Layer Stack Manager (PCB)" at 12095.86,9883.22 h49.21
  text "X" at 13580.86,9883.22 h49.21
  text "AS SHOWN" at 13700.86,9883.22 h49.21
  text "LAYER CONSTRUCTION PER:" at 10700.86,9878.22 h49.21
  text "MID LAYER 1" at 6302.34,9837.56 h49.21
  text "L1" at 6803.56,9834.06 h49.21
  text "-  COPPER CLAD" at 7848.33,9831.9 h29.53
  text "-  35 Micron H.T.E 1.4mil" at 8277.09,9832.01 h29.53
  text "-  CORE" at 7874.09,9779.08 h29.53
  text "-  10mil" at 8277.09,9779.02 h29.53
  text "Altium Designer 6.8" at 13694.53,9773.5 h49.21
  text "ARTWORK:" at 10700.86,9768.22 h49.21
  text "MANUAL" at 11600.86,9768.22 h49.21
  text "DIGITISED" at 12300.86,9768.22 h49.21
  text "X" at 12880.86,9768.22 h49.21
  text "CAD" at 13000.86,9768.22 h49.21
  text "TYPE" at 13430.86,9768.22 h49.21
  text "-  35 Micron H.T.E 1.4mil" at 8277.09,9725 h29.53
  text "-  COPPER CLAD" at 7848.33,9724.4 h29.53
  text "MID LAYER 2" at 6303.24,9717.09 h49.21
  text "L2" at 6803.24,9717.09 h49.21
  text "-  1080 5mil" at 8277.09,9675 h29.53
  text "-  PRE-PREG" at 7873.33,9673.46 h29.53
  text "ARTWORK/PATTERN MASTER LIST" at 10700.86,9583.22 h49.21
  text "P1" at 6803.24,9577.09 h49.21
  text "-  COPPER CLAD" at 7847.56,9576.35 h29.53
  text "-  35 Micron H.T.E 1.4mil" at 8277.09,9575 h29.53
  text "INTERNAL PLANE 1" at 6118.54,9573.54 h49.21
  text "-  CORE" at 7873.32,9523.53 h29.53
  text "-  10mil" at 8277.09,9522.99 h29.53
  text "DESCRIPTION" at 10750.86,9488.22 h49.21
  text "DRAWING No./CAD FILE REF." at 11485.86,9488.22 h49.21
  text "LAYER NAME" at 13110.86,9488.22 h49.21
  text "GERBER FILE REF" at 13927.87,9485.23 h49.21
  text "-  COPPER CLAD" at 7847.56,9468.85 h29.53
  text "-  35 Micron H.T.E 1.4mil" at 8277.09,9467.99 h29.53
  text "MID LAYER 3" at 6282.32,9454.72 h49.21
  text "L3" at 6797.32,9454.72 h49.21
  text "-  PRE-PREG" at 7872.56,9417.91 h29.53
  text "-  1080 5mil" at 8277.09,9417.99 h29.53
  text "PCB FILE" at 10690.86,9388.22 h49.21
  text "2x2 Peripheral Panel" at 11492.4,9385.94 h49.21
  text "PcbDoc" at 12722.87,9385.23 h49.21
  text "INTERNAL PLANE 2" at 6092.32,9329.72 h49.21
  text "P2" at 6792.32,9329.72 h49.21
  text "-  COPPER CLAD" at 7846.8,9320.8 h29.53
  text "-  35 Micron H.T.E 1.4mil" at 8277.09,9321.02 h29.53
  text "Top Paste Mask" at 13044.88,9288.22 h49.21
  text "GTP" at 12769.31,9286.28 h49.21
  text "GTP" at 14722.87,9285.23 h49.21
  text "GERBER FILE" at 10690.86,9283.22 h49.21
  text "-  CORE" at 7872.56,9267.98 h29.53
  text "-  10mil" at 8277.09,9267.99 h29.53
  text "-  COPPER CLAD" at 7846.8,9213.3 h29.53
  text "-  35 Micron H.T.E 1.4mil" at 8277.09,9212.99 h29.53
  text "MID LAYER 4" at 6301.74,9205.99 h49.21
  text "L4" at 6801.74,9205.99 h49.21
  text "GTO" at 12769.31,9187.85 h49.21
  text "GTO" at 14720.86,9187.23 h49.21
  text "Top Overlay" at 13044.88,9186.21 h49.21
  text "GERBER FILE" at 10690.86,9183.22 h49.21
  text "-  PRE-PREG" at 7871.8,9162.36 h29.53
  text "-  1080 5mil" at 8277.09,9162.01 h29.53
  text "Top Solder Mask" at 13044.88,9090.23 h49.21
  text "GTS" at 12769.31,9089.43 h49.21
  text "GTS" at 14722.87,9085.23 h49.21
  text "GERBER FILE" at 10690.86,9083.22 h49.21
  text "BL" at 6801.73,9065.98 h49.21
  text "-  35 Micron H.T.E 1.4mil" at 8277.09,9066.02 h29.53
  text "BOTTOM LAYER" at 6224.84,9065.67 h49.21
  text "-  COPPER CLAD" at 7846.04,9065.25 h29.53
  text "Board Layer 1" at 13925.2,8992.13 h49.21
  text "Top Layer" at 13044.88,8988.23 h49.21
  text "GTL" at 14722.87,8985.23 h49.21
  text "GERBER FILE" at 10690.86,8983.22 h49.21
  text "GTL" at 12769.31,8983.13 h49.21
  text "GERBER FILE" at 10690.86,8885.58 h49.21
  text "Mid Layer 1" at 13053.86,8789.06 h49.21
  text "1.6mm" at 7486.25,8788.08 h49.21
  text "G1" at 12767.72,8787.4 h49.21
  text "Board Layer 2" at 13933.07,8787.4 h49.21
  text "G1" at 14724.41,8787.4 h49.21
  text "GERBER FILE" at 10690.86,8785.58 h49.21
  text "TOTAL BOARD THICKNESS: APPROX" at 6205.16,8782.2 h49.21
  text "(61.2mil)" at 7752.4,8782.2 h49.21
  text "Board Layer 3" at 13927.87,8694.57 h49.21
  text "G2" at 12767.72,8688.98 h49.21
  text "G2" at 14724.41,8688.98 h49.21
  text "Mid Layer 2" at 13053.86,8686.69 h49.21
  text "GERBER FILE" at 10690.86,8685.58 h49.21
  text "V-GROOVE" at 9763.78,8657.48 h49.21 r90
  text "V-GROOVE" at 456.69,8606.3 h49.21 r90
  text "Board Layer 4" at 13923.94,8592.2 h49.21
  text "GP1" at 12767.72,8590.55 h49.21
  text "GP1" at 14724.41,8590.55 h49.21
  text "GND" at 13042.03,8588.29 h49.21
  text "GERBER FILE" at 10690.86,8585.58 h49.21
  text "Board Layer 5" at 13925.2,8496.06 h49.21
  text "G3" at 12762.52,8486.26 h49.21
  text "G3" at 14719.21,8486.26 h49.21
  text "GERBER FILE" at 10690.86,8484 h49.21
  text "Mid Layer 3" at 13038.11,8481.97 h49.21
  text "Board Layer 6" at 13923.94,8395.35 h49.21
  text "GP2" at 12757.52,8384.68 h49.21
  text "GP2" at 14714.21,8384.68 h49.21
  text "GERBER FILE" at 10690.86,8384 h49.21
  text "V-GROOVE" at 4917.32,8381.89 h49.21 r90
  text "V-GROOVE" at 5311.02,8381.89 h49.21 r90
  text "VCC" at 13031.5,8381.89 h49.21
  text "G4" at 12767.72,8291.34 h49.21
  text "Board Layer 7" at 13921.26,8291.34 h49.21
  text "G4" at 14724.41,8291.34 h49.21
  text "Mid Layer 4" at 13045.98,8289.06 h49.21
  text "GERBER FILE" at 10690.86,8284 h49.21
  text "GERBER FILE" at 10690.86,8184 h49.21
  text "BOTTOM LAYER" at 13037.75,8089.79 h49.21
  text "GBL" at 12762.19,8086.91 h49.21
  text "GBL" at 14715.75,8086.8 h49.21
  text "GERBER FILE" at 10690.86,8086.37 h49.21
  text "Board Layer 8" at 13913.39,8086.61 h49.21
  text "GBS" at 12762.19,7992.42 h49.21
  text "Bottom Solder Mask" at 13037.75,7991.8 h49.21
  text "GBS" at 14715.75,7986.8 h49.21
  text "GERBER FILE" at 10690.86,7986.37 h49.21
  text "GBO" at 12762.19,7890.06 h49.21
  text "Bottom Overlay" at 13037.75,7889.79 h49.21
  text "GBO" at 14715.75,7886.8 h49.21
  text "GERBER FILE" at 10690.86,7886.37 h49.21
  text "GBP" at 14715.75,7791.8 h49.21
  text "Bottom Paste Mask" at 13037.75,7789.79 h49.21
  text "GBP" at 12762.19,7787.85 h49.21
  text "GERBER FILE" at 10690.86,7786.37 h49.21
  text "APERTURE LIST" at 10690.86,7588.48 h49.21
  text "APR" at 12762.24,7585.48 h49.21
  text "DRILL REPORT" at 10690.86,7488.48 h49.21
  text "DRR" at 12762.24,7485.48 h49.21
  text "DRILL FILE" at 10680.39,7385.84 h49.21
  text "DRL" at 12757.32,7380.17 h49.21
  text "V-GROOVE" at -1188.98,7322.83 h49.21
  text "TXT" at 12751.26,7285.44 h49.21
  text "EXCELLON DRILL" at 10677.44,7282.49 h49.21
  text "MATERIAL:" at 10700.86,7077.56 h49.21
  text "GLASS FIBRE EPOXY RESIN NEMA GRADE FR4-08 (IPC-4101) - WITH TG170" at 11710.87,7067.56 h49.21
  text "X" at 11605.86,7062.56 h49.21
  text "THICKNESS:" at 11010.86,6952.56 h49.21
  text "0.8mm" at 11710.86,6952.56 h49.21
  text "1.2mm" at 12405.86,6952.56 h49.21
  text "1.6mm" at 13100.85,6952.58 h49.21
  text "2.4mm" at 13800.86,6952.56 h49.21
  text "3.2mm" at 14500.86,6952.56 h49.21
  text "X" at 13005.86,6947.56 h49.21
  text "2" at 12854.33,6838.58 h49.21
  text "TOLERANCE:" at 11005.86,6832.56 h49.21
  text "OTHER +/-" at 13800.86,6832.56 h49.21
  text "X" at 11605.86,6827.56 h49.21
  text "IN A/W IPC-D-300G CLASS" at 11732.36,6824.68 h49.21
  text "2" at 12854.33,6716.54 h49.21
  text "BOW & TWIST:" at 11005.35,6712.56 h49.21
  text "AS SHOWN" at 13805.86,6707.56 h49.21
  text "IN A/W IPC-D-300G CLASS" at 11732.36,6704.68 h49.21
  text "X" at 11605.86,6702.56 h49.21
  text "COPPER THICKNESS (FINISHED)" at 10909.45,6594.49 h49.21
  text "18um" at 11710.86,6492.56 h49.21
  text "35um" at 12775.86,6492.56 h49.21
  text "70um" at 13810.86,6492.56 h49.21
  text "OUTER:" at 11051.18,6488.19 h49.21
  text "X" at 12667.87,6484.57 h49.21
  text "INNER SIGNAL:" at 10909.45,6377.95 h49.21
  text "18um" at 11710.86,6372.56 h49.21
  text "35um" at 12775.86,6372.56 h49.21
  text "70um" at 13810.86,6372.56 h49.21
  text "X" at 11606.3,6370.08 h49.21
  text "INNER PWR:" at 11051.18,6251.97 h49.21
  text "18um" at 11710.86,6252.56 h49.21
  text "35um" at 12775.86,6252.56 h49.21
  text "70um" at 13810.86,6252.56 h49.21
  text "X" at 11606.3,6248.03 h49.21
  text "STRUCTURE:" at 10700.86,6132.56 h49.21
  text "REFER" at 11710.86,6132.56 h49.21
  text "AS PER DRAWING No." at 11705.86,6007.56 h49.21
  text "AS SHOWN" at 13805.86,6007.56 h49.21
  text "X" at 13705.86,6002.56 h49.21
  text "DRILLING:" at 10700.86,5897.56 h49.21
  text "COMPONENT SIDE" at 11710.86,5807.56 h49.21
  text "SOLDER SIDE" at 12765.86,5807.56 h49.21
  text "VIEWED FROM:" at 10976.38,5799.21 h49.21
  text "X" at 11605.86,5797.56 h49.21
  text "REFERENCE:" at 10985.86,5687.56 h49.21
  text "AS SHOWN" at 11705.86,5682.56 h49.21
  text "PATTERN MASTER LIST" at 12770.86,5682.56 h49.21
  text "X" at 13705.86,5682.56 h49.21
  text "NC_DRILL FILES" at 13805.86,5682.56 h49.21
  text "X" at 11605.86,5677.56 h49.21
  text "20um" at 12775.86,5567.56 h49.21
  text "PTH MINIMUM COPPER THICKNESS:" at 10988.19,5562.99 h49.21
  text "X" at 12670.86,5562.56 h49.21
  text "OTHER" at 13805.86,5562.56 h49.21
  text "NPTH:" at 10984.25,5448.82 h49.21
  text "TENTED" at 11705.86,5442.56 h49.21
  text "X" at 12670.86,5442.56 h49.21
  text "PADS REMOVED" at 12770.86,5442.56 h49.21
  text "REMOVE PADS" at 13805.86,5442.56 h49.21
  text "X" at 11605.86,5437.56 h49.21
  text "2nd DRILL" at 11705.86,5322.56 h49.21
  text "BOTH" at 12770.86,5322.56 h49.21
  text "AS SHOWN" at 13255.86,5322.56 h49.21
  text "NONE" at 13805.86,5322.56 h49.21
  text "BOARD FINISH:" at 10700.86,5207.56 h49.21
  text "X" at 11605.86,5202.56 h49.21
  text "ETCHING" at 11705.86,5202.56 h49.21
  text "REFER PATTERN MASTER LIST" at 12770.86,5202.56 h49.21
  text "NONE" at 12039.45,5086.93 h49.21
  text "LEGEND / SCREEN PRINT:" at 10952.76,5086.61 h49.21
  text "COMPONENT" at 12770.75,5085.55 h49.21
  text "SOLDER" at 13807.17,5082.99 h49.21
  text "X" at 12670.75,5080.55 h49.21
  text "X" at 13707.17,5077.99 h49.21
  text "WHITE" at 11708.74,4972.76 h49.21
  text "COLOUR:" at 11185.04,4968.5 h49.21
  text "X" at 11608.74,4967.76 h49.21
  text "YELLOW" at 12770.86,4962.56 h49.21
  text "OTHER" at 13805.86,4962.56 h49.21
  text "SOLDER RESIST:" at 10944.88,4842.52 h49.21
  text "X" at 11605.86,4842.56 h49.21
  text "LIQUID PHOTOIMAGEABLE" at 11705.86,4842.56 h49.21
  text "SCREEN PRINT" at 13255.86,4842.56 h49.21
  text "FINISH:" at 11196.85,4724.41 h49.21
  text "MATTE" at 11705.86,4722.56 h49.21
  text "GLOSS" at 12205.86,4722.56 h49.21
  text "X" at 12100.86,4717.56 h49.21
  text "COLOUR:" at 11185.04,4606.3 h49.21
  text "BLACK" at 11705.86,4602.56 h49.21
  text "GREEN" at 12205.86,4602.56 h49.21
  text "YELLOW" at 12770.86,4602.56 h49.21
  text "BLUE" at 13255.86,4602.56 h49.21
  text "OTHER" at 13805.86,4602.56 h49.21
  text "X" at 11600.86,4597.56 h49.21
  text "TRACK FINISH:" at 10700.86,4487.56 h49.21
  text "SELECTIVE SOLDER (HASL)" at 11705.86,4482.56 h49.21
  text "REFLOW SOLDER" at 13255.86,4482.56 h49.21
  text "0.1um - 0.2um ELECTROLESS GOLD OVER 3um NICKEL" at 11708.66,4370.08 h49.21
  text "X" at 11606.3,4366.14 h49.21
  text "IMMERSION GOLD" at 11705.86,4242.56 h49.21
  text "OTHER" at 13255.86,4242.56 h49.21
  text "EDGE BOARD" at 10700.86,4127.56 h49.21
  text "1.3um HARD GOLD OVER 5um     NICKEL / TIN-NICKEL" at 11705.86,4122.56 h49.21
  text "V-GROOVE" at -1181.1,4082.68 h49.21
  text "CONTACTS:" at 10700.86,4042.56 h49.21
  text "HARD FINISH GOLDE PLATE" at 11705.86,4002.56 h49.21
  text "OTHER" at 13255.86,4002.56 h49.21
  text "AS SHOWN" at 11705.86,3882.56 h49.21
  text "REFER" at 13255.86,3882.56 h49.21
  text "PROFILING:" at 10700.86,3762.56 h49.21
  text "AS DIMENSIONED, MEASURED AND CUT FROM SPECIFIED DATUM." at 11705.86,3762.56 h49.21
  text "X" at 11605.86,3757.56 h49.21
  text "V-GROOVE" at -1161.42,3688.98 h49.21
  text "REFER PCB BLANK DWG No." at 11710.86,3647.56 h49.21
  text "USE PROFILE / ROUTE TAPE SUPPLIED (REFER PATTERN MASTER LIST)" at 11710.86,3527.56 h49.21
  text "X" at 13000,3409.45 h49.21
  text "SQUARE CUT" at 11710.86,3407.56 h49.21
  text "N.C. ROUTE" at 12410.86,3407.56 h49.21
  text "V. SCORE" at 13110.86,3407.56 h49.21
  text "BLANK" at 13810.86,3407.56 h49.21
  text "ACCEPTABILITY:" at 10700.86,3302.56 h49.21
  text "MATERIALS AND WORKMANSHIP FOR ALL PRINTED WIRING BOARDS TO MEET" at 11575.86,3297.56 h49.21
  text "OR EXCEED THE REQUIREMENTS OF:" at 11575.86,3187.56 h49.21
  text "IPC-6011/12 AND IPC-A-600E" at 11715.86,3082.56 h49.21
  text "1" at 13115.86,3082.56 h49.21
  text "2" at 13465.86,3082.56 h49.21
  text "3" at 13816.1,3080.12 h49.21
  text "X" at 13360.86,3077.56 h49.21
  text "X" at 11610.86,3072.56 h49.21
  text "UL CERTIFICATION" at 11715.86,2962.56 h49.21
  text "AUSTEL" at 13115.86,2962.56 h49.21
  text "X" at 11610.86,2957.56 h49.21
  text "ML-P-55110F GRP" at 11695.86,2842.56 h49.21
  text "A" at 12415.86,2842.56 h49.21
  text "B" at 12765.86,2842.56 h49.21
  text "AS2546" at 13115.86,2842.56 h49.21
  text "OTHER" at 13815.86,2842.56 h49.21
  text "ADDITIONAL REQUIREMENTS:" at 10692.91,2712.6 h49.21
  text "NONE" at 11714.53,2611.1 h49.21
  text "SAMPLE PLAN" at 12414.53,2611.1 h49.21
  text "MIL-P-55110E SERIAL Nos. PER ORDER" at 13193.27,2611.1 h49.21
  text "X" at 11608.27,2610.51 h49.21
  text "MICROSECTION:" at 10897.64,2606.3 h49.21
  text "NONE" at 11718.27,2485.59 h49.21
  text "CERTIFICATION:" at 10893.7,2480.32 h49.21
  text "A" at 13191.46,2476.42 h49.21
  text "MIL-P-55110E GRP" at 12410.2,2474.45 h49.21
  text "B" at 13402.72,2473.31 h49.21
  text "1" at 14375.16,2469.37 h49.21
  text "2" at 14586.42,2466.26 h49.21
  text "3" at 14802.95,2466.26 h49.21
  text "IPC CLASS:" at 13807.84,2462.64 h49.21
  text "RoHS Compliant" at 11718.27,2359.61 h49.21
  text "X" at 11608.27,2354.61 h49.21
  text "X" at 12306.61,2351.1 h49.21
  text "QUALITY RELEASE REPORT" at 12410.2,2348.46 h49.21
  text "OTHER" at 13811.93,2346.5 h49.21
  text "NONE" at 11716.1,2233.15 h49.21
  text "REQUIRED (100% PADS & NETS)" at 12416.1,2233.15 h49.21
  text "PER ORDER" at 13820.04,2229.21 h49.21
  text "ELECTRICAL TEST:" at 10893.7,2228.35 h49.21
  text "X" at 12311.1,2228.15 h49.21
  text "NONE" at 11716.1,2107.17 h49.21
  text "1 SIDE" at 12411.1,2107.17 h49.21
  text "2 SIDES" at 13178.94,2107.68 h49.21
  text "MIN. PITCH" at 13812.17,2107.68 h49.21
  text "0.6mm" at 14347.17,2107.68 h49.21
  text "SURFACE MOUNT:" at 10889.76,2102.36 h49.21
  text "X" at 13090.94,2099.69 h49.21
  text "FOIL" at 13194.84,1983.54 h49.21
  text "Bottom Overlay" at 14330.95,1980.16 h49.21
  text "NONE" at 12416.1,1979.61 h49.21
  text "LEGEND" at 13538.54,1979.61 h49.21
  text "REFER" at 14011.1,1979.61 h49.21
  text "X" at 13432.6,1978.07 h49.21
  text "X" at 13905.04,1978.07 h49.21
  text "MANUFACTURER'S ID/LOGO:" at 10889.76,1968.5 h49.21
  text "NONE" at 13196.85,1858.27 h49.21
  text "ISO9001/AS3901" at 12416.89,1851.26 h49.21
  text "MANUFACTURER'S ACCREDITATION:" at 10889.76,1846.46 h49.21
  text "X" at 12311.89,1846.26 h49.21
  text "PACKAGING AND HANDLING:" at 10889.76,1736.22 h49.21
  text "REFER" at 13194.84,1727.8 h49.21
  text "PER ORDER" at 12416.1,1723.86 h49.21
  text "X" at 12311.1,1713.86 h49.21
  text "Notes" at 10590.55,1421.26 h49.21
  text "1. All dimensions are in mm." at 10656.3,1191.73 h49.21
  text "2. Controlled impedance traces are on TOP, MID1, MID2, MID3," at 10641.73,929.13 h49.21
  text "MID4 and BOTTOM layers are 50 ohm single-ended, which is" at 10799.21,732.28 h49.21
  text "achieved with 5 mil traces (on all layers)." at 10799.21,535.43 h49.21
  text "V-GROOVE" at -1177.17,460.63 h49.21
  text "3. Details for V-grooves and break off." at 10653.54,228.35 h49.21
  text "0.07" at 12215.83,-12.44 h49.21 r90
  text "+" at 12195.83,-102.44 h49.21 r90
  text "-" at 12245.83,-102.44 h49.21 r90
  text "0.40" at 12215.83,-362.44 h49.21 r90
  text "Panel boundary coincides with centre-lines of tracks" at 0,-1248.03 h49.21
  text ".Printout_Name" at 3484.25,-1248.03 h49.21
  text "0.1 MAX. DEVIATION" at 11650.83,-1337.44 h49.21
  text "Dimensions in millimetres" at 3.94,-1405.51 h49.21

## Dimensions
4850.39,326.77 to 393.7,-11.81 on 6. FabNotes
0,0 to 10094.49,0 on 6. FabNotes
0,0 to 0,480.31 on 6. FabNotes
10094.49,90.55 to 9700.79,484.25 on 6. FabNotes
393.7,62.99 to 0,456.69 on 6. FabNotes
4850.39,94.49 to 5244.09,94.49 on 6. FabNotes
0,0 to 0,7826.77 on 6. FabNotes
0,7346.46 to 0,7826.77 on 6. FabNotes
0,3716.54 to -7.87,4110.24 on 6. FabNotes
0,4110.24 to -7.87,7346.46 on 6. FabNotes
0,480.31 to -7.87,3716.54 on 6. FabNotes
9700.79,326.77 to 5244.09,-11.81 on 6. FabNotes

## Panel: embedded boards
"DB42.PcbDoc" at 9700.79,480.31, 2 rows x 2 columns, spacing 4850.39 x 3629.92, rotation 90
